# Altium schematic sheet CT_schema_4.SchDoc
size 218 x 258 mm
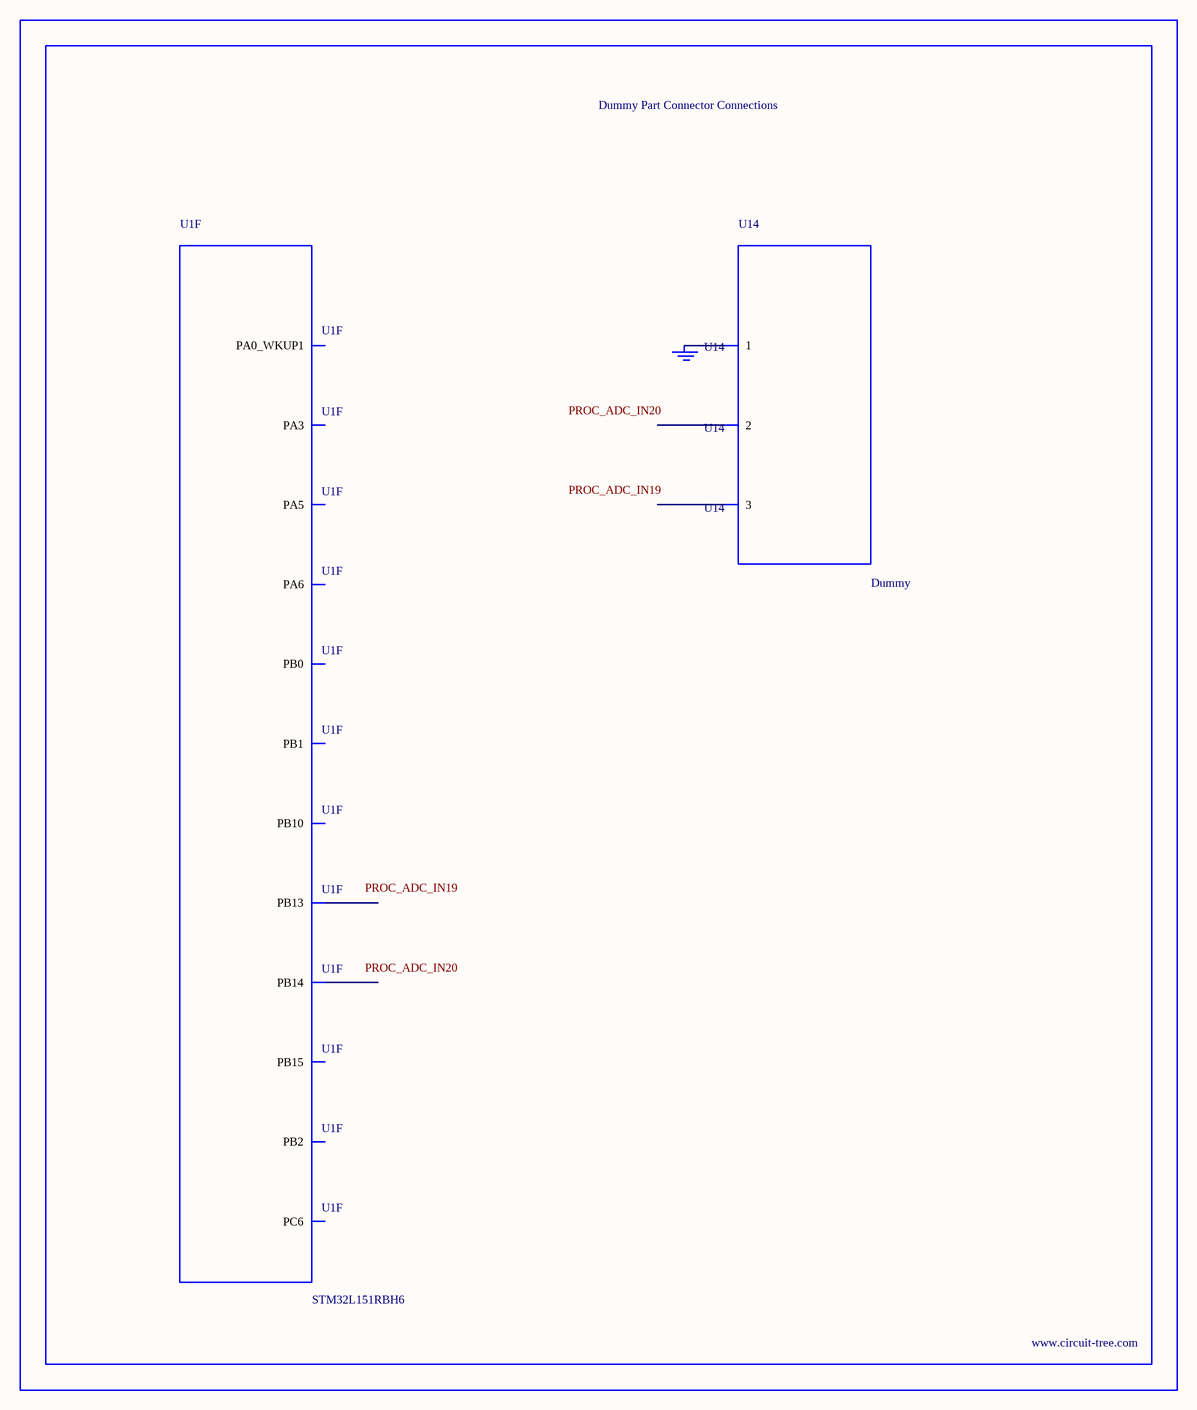
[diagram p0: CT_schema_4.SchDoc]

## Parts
BORDER3  (no value)
GND_INSTANCE_3_0  (no value)
U1  STM32L151RBH6  [TFBGA64]  (part F of 6)
U14  Dummy  [DUMMY_PACKAGE_110]

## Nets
NetGND_INSTANCE_3_0_0: GND_INSTANCE_3_0.0(GND) U14.1

Not connected (* = marked no-connect by the designer): U1 F4(PA5) F5(PB0) F6(PC6) F7(PB15) F8(PB14) G2(PA0_WKUP1) G3(PA3) G4(PA6) G5(PB1) G6(PB2) G7(PB10) G8(PB13); U14 2 3

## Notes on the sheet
- Labels drawn without touching a wire or pin: PROC_ADC_IN19, PROC_ADC_IN20

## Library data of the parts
BORDER3 = BORDER_PAGE3
GND_INSTANCE_3_0 = GND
